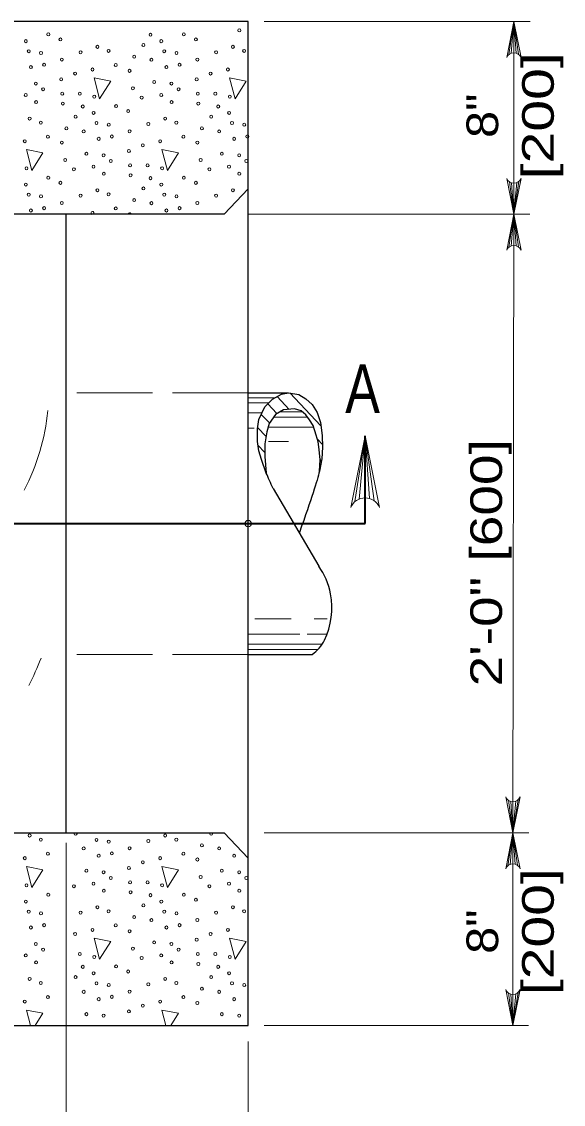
# Model space of a CAD drawing. Extents: x -410.5 to -376.5, y 1617.6 to 1661.6.
# Drawn here: x -401.85 to -399.18, y 1643.03 to 1648.36 of the extents above; entities that cross this region are included whole.
import ezdxf
from ezdxf.enums import TextEntityAlignment as Align

# ---------------------------------------------------------------- set-up
doc = ezdxf.new("R2010")
doc.units = 0
doc.header["$LTSCALE"] = 0.062
doc.header["$PDMODE"] = 32
doc.header["$PDSIZE"] = 0.031
doc.linetypes.add('LONG_DASHED', pattern=[7.5, 6, -1.5])
doc.layers.add('1', color=7, linetype='Continuous', lineweight=13)

msp = doc.modelspace()

# ---------------------------------------------------------------- linework, layer by layer
at = {"layer": '1'}
for p, q in [((-399.345, 1648.3615), (-400.65567, 1648.3615)), ((-399.44992, 1648.19942), (-399.42517, 1648.3615)), ((-399.4395, 1648.2055), (-399.42517, 1648.3615)), ((-399.42517, 1648.3615), (-399.42517, 1647.41208)), ((-399.42517, 1648.20833), (-399.42517, 1648.3615)), ((-399.41383, 1648.20667), (-399.42517, 1648.3615)), ((-399.40267, 1648.20125), (-399.42517, 1648.3615)), ((-400.74375, 1648.06817), (-400.82575, 1648.08408)), ((-399.44758, 1647.57233), (-399.42517, 1647.41208)), ((-399.43642, 1647.56692), (-399.42517, 1647.41208)), ((-399.40033, 1647.57417), (-399.42517, 1647.41208)), ((-399.41075, 1647.56808), (-399.42517, 1647.41208)), ((-399.42517, 1647.56525), (-399.42517, 1647.41208)), ((-399.3465, 1647.41208), (-400.73433, 1647.41208)), ((-399.44992, 1647.24992), (-399.42517, 1647.41208)), ((-399.4395, 1647.25608), (-399.42517, 1647.41208)), ((-399.42517, 1647.41208), (-399.42975, 1644.36383)), ((-399.42517, 1647.25892), (-399.42517, 1647.41208)), ((-399.41383, 1647.25725), (-399.42517, 1647.41208)), ((-399.40267, 1647.25183), (-399.42517, 1647.41208)), ((-400.73433, 1646.508), (-400.60125, 1646.508)), ((-400.59167, 1646.51333), (-400.53217, 1646.45025)), ((-400.529, 1646.53167), (-400.376, 1646.36975)), ((-400.73433, 1646.483), (-400.63208, 1646.483)), ((-400.63783, 1646.47725), (-400.59275, 1646.42958)), ((-400.73433, 1646.43308), (-400.66625, 1646.43308)), ((-400.6695, 1646.42608), (-400.62967, 1646.38392)), ((-400.60917, 1646.41292), (-400.4425, 1646.41292)), ((-400.57825, 1646.43792), (-400.46692, 1646.43792)), ((-400.73433, 1646.35808), (-400.704, 1646.35808)), ((-400.68775, 1646.36058), (-400.64608, 1646.31642)), ((-400.63642, 1646.36292), (-400.412, 1646.36292)), ((-400.63492, 1646.29217), (-400.536, 1646.29217)), ((-400.3935, 1646.30342), (-400.36875, 1646.27733)), ((-400.208, 1645.99633), (-400.1585, 1646.32058)), ((-400.18725, 1646.00858), (-400.1585, 1646.32058)), ((-400.1585, 1646.01425), (-400.1585, 1646.32058)), ((-400.13583, 1646.011), (-400.1585, 1646.32058)), ((-400.11367, 1646.00008), (-400.1585, 1646.32058)), ((-400.68583, 1646.27383), (-400.65225, 1646.23825)), ((-400.37992, 1646.20433), (-400.37367, 1646.19767)), ((-400.37983, 1646.20175), (-400.374, 1646.1955)), ((-400.65, 1646.151), (-400.64575, 1646.1465)), ((-400.64617, 1646.14042), (-400.645, 1646.13933)), ((-400.38167, 1646.16833), (-400.37933, 1646.16592)), ((-400.70208, 1645.41783), (-400.52225, 1645.41783)), ((-400.409, 1645.41783), (-400.34525, 1645.41783)), ((-400.73433, 1645.34283), (-400.47942, 1645.34283)), ((-400.44417, 1645.34283), (-400.34525, 1645.34283)), ((-400.73433, 1645.29283), (-400.37, 1645.29283)), ((-400.73433, 1645.26792), (-400.39025, 1645.26792)), ((-399.45217, 1644.52408), (-399.42975, 1644.36383)), ((-399.44108, 1644.51867), (-399.42975, 1644.36383)), ((-399.40492, 1644.52592), (-399.42975, 1644.36383)), ((-399.41533, 1644.51983), (-399.42975, 1644.36383)), ((-399.42975, 1644.517), (-399.42975, 1644.36383)), ((-399.35108, 1644.36383), (-400.65567, 1644.36383)), ((-399.4545, 1644.20167), (-399.42975, 1644.36383)), ((-399.44408, 1644.20783), (-399.42975, 1644.36383)), ((-399.42975, 1644.21067), (-399.42975, 1644.36383)), ((-399.41842, 1644.209), (-399.42975, 1644.36383)), ((-399.40733, 1644.20358), (-399.42975, 1644.36383)), ((-399.42975, 1644.36383), (-399.42975, 1643.41433)), ((-401.631, 1644.31375), (-401.631, 1642.69667)), ((-400.82575, 1643.84383), (-400.79875, 1643.7415)), ((-400.74375, 1643.828), (-400.82575, 1643.84383)), ((-400.79875, 1643.7415), (-400.74375, 1643.828)), ((-399.45217, 1643.57458), (-399.42975, 1643.41433)), ((-399.44108, 1643.56917), (-399.42975, 1643.41433)), ((-399.40492, 1643.5765), (-399.42975, 1643.41433)), ((-399.41533, 1643.57033), (-399.42975, 1643.41433)), ((-399.42975, 1643.5675), (-399.42975, 1643.41433)), ((-401.827, 1643.49058), (-401.80683, 1643.41433)), ((-401.745, 1643.47458), (-401.827, 1643.49058)), ((-401.78333, 1643.41433), (-401.745, 1643.47458)), ((-401.15942, 1643.49058), (-401.13933, 1643.41433)), ((-401.0775, 1643.47458), (-401.15942, 1643.49058)), ((-401.11583, 1643.41433), (-401.0775, 1643.47458)), ((-399.3525, 1643.41433), (-400.65567, 1643.41433)), ((-400.73417, 1643.33558), (-400.73417, 1642.69667))]:
    msp.add_line(p, q, dxfattribs=at)
at = {"layer": '1', "lineweight": 25}
for p, q in [((-400.8525, 1647.41208), (-400.7345, 1647.537)), ((-400.8525, 1647.41208), (-401.63108, 1647.41208)), ((-400.73433, 1646.533), (-400.5355, 1646.533)), ((-400.61067, 1646.0605), (-400.38658, 1645.67742)), ((-400.73433, 1645.24292), (-400.41833, 1645.24292)), ((-401.63108, 1644.36375), (-400.8525, 1644.36383)), ((-400.8525, 1644.36383), (-400.7345, 1644.23892))]:
    msp.add_line(p, q, dxfattribs=at)
at = {"layer": '1', "linetype": 'LONG_DASHED'}
for p, q in [((-400.73433, 1646.533), (-401.63108, 1646.533)), ((-400.73433, 1645.24292), (-401.63108, 1645.24292))]:
    msp.add_line(p, q, dxfattribs=at)
at = {"layer": '1', "lineweight": 35}
for p, q in [((-400.1585, 1645.88792), (-400.1585, 1646.32058)), ((-402.19475, 1645.88792), (-400.1585, 1645.88792))]:
    msp.add_line(p, q, dxfattribs=at)
at = {"layer": '1', "lineweight": 25}
msp.add_lwpolyline([(-405.35992, 1643.41425), (-400.73433, 1643.41425), (-400.73433, 1648.3615), (-405.35992, 1648.3615), (-405.35992, 1647.537), (-405.35992, 1644.23892)], close=True, dxfattribs=at)
at = {"layer": '1'}
for points in [[(-399.4605, 1648.1845), (-399.42517, 1648.3615), (-399.38975, 1648.1845)], [(-400.82575, 1648.08408), (-400.79875, 1647.98167), (-400.74375, 1648.06817)], [(-399.38975, 1647.58908), (-399.42517, 1647.41208), (-399.4605, 1647.58908)], [(-399.4605, 1647.23508), (-399.42517, 1647.41208), (-399.38975, 1647.23508)], [(-400.22925, 1645.96658), (-400.1585, 1646.32058), (-400.08767, 1645.96658)], [(-399.39433, 1644.54083), (-399.42975, 1644.36383), (-399.46508, 1644.54083)], [(-399.46508, 1644.18683), (-399.42975, 1644.36383), (-399.39433, 1644.18683)], [(-399.39433, 1643.59133), (-399.42975, 1643.41433), (-399.46508, 1643.59133)]]:
    msp.add_lwpolyline(points, dxfattribs=at)
for points in [[(-401.49325, 1648.08408), (-401.46625, 1647.98167), (-401.41125, 1648.06817)], [(-401.827, 1647.73075), (-401.8, 1647.62833), (-401.745, 1647.71483)], [(-401.15942, 1647.73075), (-401.13242, 1647.62833), (-401.0775, 1647.71483)], [(-401.827, 1644.19725), (-401.8, 1644.09483), (-401.745, 1644.18125)], [(-401.15942, 1644.19725), (-401.13242, 1644.09483), (-401.0775, 1644.18125)], [(-401.49325, 1643.84383), (-401.46625, 1643.7415), (-401.41125, 1643.828)]]:
    msp.add_lwpolyline(points, close=True, dxfattribs=at)
at = {"layer": '1', "lineweight": 25}
for points in [[(-404.46308, 1644.36383), (-404.46308, 1644.36375), (-401.63108, 1644.36375), (-401.63108, 1647.41208), (-404.46308, 1647.41208)], [(-400.64483, 1646.13692), (-400.66917, 1646.203), (-400.68133, 1646.24617), (-400.689, 1646.29242), (-400.68875, 1646.35433), (-400.68092, 1646.4015), (-400.6525, 1646.46275), (-400.61383, 1646.501), (-400.57067, 1646.52508), (-400.5355, 1646.533), (-400.48517, 1646.52333), (-400.4505, 1646.50292), (-400.41842, 1646.475), (-400.39408, 1646.43592), (-400.378, 1646.3865), (-400.37, 1646.32242), (-400.36833, 1646.265), (-400.37208, 1646.20617), (-400.38283, 1646.14692)], [(-400.64483, 1646.13692), (-400.66917, 1646.203), (-400.68133, 1646.24617), (-400.689, 1646.29242), (-400.68875, 1646.35433), (-400.68092, 1646.4015), (-400.6525, 1646.46275), (-400.61383, 1646.501), (-400.57067, 1646.52508), (-400.5355, 1646.533), (-400.48517, 1646.52333), (-400.4505, 1646.50292), (-400.41842, 1646.475), (-400.39408, 1646.43592), (-400.378, 1646.3865), (-400.37, 1646.32242), (-400.36833, 1646.265), (-400.37208, 1646.20617), (-400.38283, 1646.14692)], [(-400.38283, 1646.14692), (-400.37975, 1646.20275), (-400.38442, 1646.25233), (-400.38992, 1646.29025), (-400.39908, 1646.32425), (-400.41467, 1646.37092), (-400.43217, 1646.39917), (-400.4505, 1646.4235), (-400.47258, 1646.44283), (-400.50567, 1646.45258), (-400.56067, 1646.44775), (-400.60025, 1646.42542), (-400.63142, 1646.38167), (-400.6425, 1646.33983), (-400.65167, 1646.28058), (-400.65258, 1646.21925), (-400.64483, 1646.13692)], [(-400.38283, 1646.14692), (-400.37975, 1646.20275), (-400.38442, 1646.25233), (-400.38992, 1646.29025), (-400.39908, 1646.32425), (-400.41467, 1646.37092), (-400.43217, 1646.39917), (-400.4505, 1646.4235), (-400.47258, 1646.44283), (-400.50567, 1646.45258), (-400.56067, 1646.44775), (-400.60025, 1646.42542), (-400.63142, 1646.38167), (-400.6425, 1646.33983), (-400.65167, 1646.28058), (-400.65258, 1646.21925), (-400.64483, 1646.13692)]]:
    msp.add_lwpolyline(points, dxfattribs=at)
at = {"layer": '1'}
for centre, radius, start, end in [((-399.42509, 1648.17022), 0.0382, 22.08782, 157.91395), ((-399.42516, 1647.60336), 0.0382, 202.08782, 337.91395), ((-399.42509, 1647.22077), 0.0382, 22.08782, 157.91395), ((-400.1584, 1645.93802), 0.0764, 22.08782, 157.91395), ((-399.42975, 1644.55511), 0.0382, 202.08782, 337.91395), ((-399.42968, 1644.17253), 0.0382, 22.08782, 157.91395), ((-399.42975, 1643.60566), 0.0382, 202.08782, 337.91395)]:
    msp.add_arc(centre, radius, start, end, dxfattribs=at)
for centre, major_axis in [((-401.71877, 1648.29871), (0, -0.00756)), ((-401.05126, 1648.29871), (0, -0.00756)), ((-400.77786, 1648.31843), (0, -0.00756)), ((-401.82963, 1648.26531), (0, 0.00756)), ((-401.65931, 1648.27391), (0, -0.00756)), ((-401.25046, 1648.24623), (0, 0.00756)), ((-401.21525, 1648.29682), (0, 0.00756)), ((-401.16213, 1648.26531), (0, 0.00756)), ((-400.9918, 1648.27391), (0, -0.00756)), ((-401.81517, 1648.21573), (0, 0.00756)), ((-401.75482, 1648.20707), (0, -0.00756)), ((-401.55985, 1648.21066), (0, -0.00756)), ((-401.47691, 1648.23734), (0, -0.00756)), ((-401.42195, 1648.21732), (0, -0.00756)), ((-401.14766, 1648.21573), (0, 0.00756)), ((-401.08731, 1648.20707), (0, -0.00756)), ((-400.89234, 1648.21066), (0, -0.00756)), ((-400.8094, 1648.23734), (0, -0.00756)), ((-400.75444, 1648.21732), (0, -0.00756)), ((-401.73952, 1648.14894), (0, -0.00756)), ((-401.65208, 1648.17462), (0, -0.00756)), ((-401.38685, 1648.14765), (0, 0.00756)), ((-401.29579, 1648.1887), (0, 0.00756)), ((-401.2108, 1648.17374), (0, 0.00756)), ((-401.07201, 1648.14894), (0, -0.00756)), ((-400.98457, 1648.17462), (0, -0.00756)), ((-401.80444, 1648.13746), (0, -0.00756)), ((-401.58694, 1648.10566), (0, -0.00756)), ((-401.50127, 1648.12568), (0, -0.00756)), ((-401.31832, 1648.11903), (0, 0.00756)), ((-401.13693, 1648.13746), (0, -0.00756)), ((-400.91943, 1648.10566), (0, -0.00756)), ((-400.83377, 1648.12568), (0, -0.00756)), ((-401.78002, 1648.05637), (0, -0.00756)), ((-401.65536, 1648.07704), (0, -0.00756)), ((-401.30208, 1648.03316), (0, -0.00756)), ((-401.19756, 1648.06373), (0, -0.00756)), ((-401.11251, 1648.05637), (0, -0.00756)), ((-400.98785, 1648.07704), (0, -0.00756)), ((-401.82991, 1647.99977), (0, -0.00756)), ((-401.74458, 1648.02839), (0, -0.00756)), ((-401.64996, 1648.00643), (0, -0.00756)), ((-401.56341, 1648.00643), (0, 0.00756)), ((-401.49226, 1647.99212), (0, -0.00756)), ((-401.2588, 1647.98735), (0, -0.00756)), ((-401.1624, 1647.99977), (0, -0.00756)), ((-401.07707, 1648.02839), (0, -0.00756)), ((-400.98245, 1648.00643), (0, -0.00756)), ((-400.8959, 1648.00643), (0, 0.00756)), ((-400.82476, 1647.99212), (0, -0.00756)), ((-401.77913, 1647.96509), (0, -0.00756)), ((-401.64729, 1647.95778), (0, -0.00756)), ((-401.549, 1647.94347), (0, 0.00756)), ((-401.38502, 1647.94536), (0, -0.00756)), ((-401.11162, 1647.96509), (0, -0.00756)), ((-400.97978, 1647.95778), (0, -0.00756)), ((-400.88149, 1647.94347), (0, 0.00756)), ((-401.81067, 1647.88399), (0, -0.00756)), ((-401.58421, 1647.89288), (0, 0.00756)), ((-401.49588, 1647.91196), (0, 0.00756)), ((-401.32555, 1647.92056), (0, -0.00756)), ((-401.14316, 1647.88399), (0, -0.00756)), ((-400.9167, 1647.89288), (0, 0.00756)), ((-400.82837, 1647.91196), (0, 0.00756)), ((-401.75571, 1647.86397), (0, -0.00756)), ((-401.62955, 1647.83535), (0, 0.00756)), ((-401.54455, 1647.82039), (0, 0.00756)), ((-401.48142, 1647.86238), (0, 0.00756)), ((-401.42106, 1647.85372), (0, -0.00756)), ((-401.31832, 1647.82127), (0, -0.00756)), ((-401.22609, 1647.85731), (0, -0.00756)), ((-401.0882, 1647.86397), (0, -0.00756)), ((-400.96204, 1647.83535), (0, 0.00756)), ((-400.87704, 1647.82039), (0, 0.00756)), ((-400.81391, 1647.86238), (0, 0.00756)), ((-400.75355, 1647.85372), (0, -0.00756)), ((-401.83503, 1647.77233), (0, -0.00756)), ((-401.72061, 1647.7943), (0, 0.00756)), ((-401.65208, 1647.76568), (0, 0.00756)), ((-401.47068, 1647.78411), (0, -0.00756)), ((-401.40577, 1647.79559), (0, -0.00756)), ((-401.16752, 1647.77233), (0, -0.00756)), ((-401.0531, 1647.7943), (0, 0.00756)), ((-400.98457, 1647.76568), (0, 0.00756)), ((-400.80317, 1647.78411), (0, -0.00756)), ((-400.73826, 1647.79559), (0, -0.00756)), ((-401.3216, 1647.72369), (0, -0.00756)), ((-401.25318, 1647.75231), (0, -0.00756)), ((-401.63583, 1647.67981), (0, -0.00756)), ((-401.53131, 1647.71038), (0, -0.00756)), ((-401.44626, 1647.70302), (0, -0.00756)), ((-401.41083, 1647.67504), (0, -0.00756)), ((-400.96833, 1647.67981), (0, -0.00756)), ((-400.8638, 1647.71038), (0, -0.00756)), ((-400.77875, 1647.70302), (0, -0.00756)), ((-400.74332, 1647.67504), (0, -0.00756)), ((-401.82602, 1647.63877), (0, -0.00756)), ((-401.59256, 1647.634), (0, -0.00756)), ((-401.49616, 1647.64642), (0, -0.00756)), ((-401.44537, 1647.61174), (0, -0.00756)), ((-401.31621, 1647.65308), (0, -0.00756)), ((-401.22965, 1647.65308), (0, 0.00756)), ((-401.15851, 1647.63877), (0, -0.00756)), ((-400.92505, 1647.634), (0, -0.00756)), ((-400.82865, 1647.64642), (0, -0.00756)), ((-400.77786, 1647.61174), (0, -0.00756)), ((-401.82963, 1647.55861), (0, 0.00756)), ((-401.71877, 1647.59201), (0, -0.00756)), ((-401.65931, 1647.56721), (0, -0.00756)), ((-401.31354, 1647.60443), (0, -0.00756)), ((-401.21525, 1647.59012), (0, 0.00756)), ((-401.16213, 1647.55861), (0, 0.00756)), ((-401.05126, 1647.59201), (0, -0.00756)), ((-400.9918, 1647.56721), (0, -0.00756)), ((-401.81517, 1647.50903), (0, 0.00756)), ((-401.75482, 1647.50037), (0, -0.00756)), ((-401.55985, 1647.50396), (0, -0.00756)), ((-401.47691, 1647.53064), (0, -0.00756)), ((-401.42195, 1647.51062), (0, -0.00756)), ((-401.25046, 1647.53953), (0, 0.00756)), ((-401.14766, 1647.50903), (0, 0.00756)), ((-401.08731, 1647.50037), (0, -0.00756)), ((-400.89234, 1647.50396), (0, -0.00756)), ((-400.8094, 1647.53064), (0, -0.00756)), ((-401.65208, 1647.46792), (0, -0.00756)), ((-401.29579, 1647.482), (0, 0.00756)), ((-401.2108, 1647.46704), (0, 0.00756)), ((-400.98457, 1647.46792), (0, -0.00756)), ((-401.80444, 1647.43076), (0, -0.00756)), ((-401.73952, 1647.44225), (0, -0.00756)), ((-401.38685, 1647.44095), (0, 0.00756)), ((-401.13693, 1647.43076), (0, -0.00756)), ((-401.07201, 1647.44225), (0, -0.00756)), ((-401.81067, 1644.35049), (0, -0.00756)), ((-401.14316, 1644.35049), (0, -0.00756)), ((-401.75571, 1644.33047), (0, -0.00756)), ((-401.48142, 1644.32888), (0, 0.00756)), ((-401.42106, 1644.32022), (0, -0.00756)), ((-401.22609, 1644.32382), (0, -0.00756)), ((-401.0882, 1644.33047), (0, -0.00756)), ((-400.96204, 1644.30185), (0, 0.00756)), ((-401.72061, 1644.2608), (0, 0.00756)), ((-401.54455, 1644.28689), (0, 0.00756)), ((-401.47068, 1644.25061), (0, -0.00756)), ((-401.40577, 1644.2621), (0, -0.00756)), ((-401.31832, 1644.28777), (0, -0.00756)), ((-401.0531, 1644.2608), (0, 0.00756)), ((-400.87704, 1644.28689), (0, 0.00756)), ((-400.80317, 1644.25061), (0, -0.00756)), ((-401.83503, 1644.23883), (0, -0.00756)), ((-401.3216, 1644.19019), (0, -0.00756)), ((-401.25318, 1644.21881), (0, -0.00756)), ((-401.16752, 1644.23883), (0, -0.00756)), ((-400.98457, 1644.23218), (0, 0.00756)), ((-401.53131, 1644.17688), (0, -0.00756)), ((-401.44626, 1644.16952), (0, -0.00756)), ((-401.41083, 1644.14155), (0, -0.00756)), ((-400.96833, 1644.14632), (0, -0.00756)), ((-400.8638, 1644.17688), (0, -0.00756)), ((-400.77875, 1644.16952), (0, -0.00756)), ((-400.74332, 1644.14155), (0, -0.00756)), ((-401.82602, 1644.10527), (0, -0.00756)), ((-401.59256, 1644.1005), (0, -0.00756)), ((-401.49616, 1644.11292), (0, -0.00756)), ((-401.31621, 1644.11958), (0, -0.00756)), ((-401.22965, 1644.11958), (0, 0.00756)), ((-401.15851, 1644.10527), (0, -0.00756)), ((-400.92505, 1644.1005), (0, -0.00756)), ((-400.82865, 1644.11292), (0, -0.00756)), ((-401.71877, 1644.05851), (0, -0.00756)), ((-401.44537, 1644.07824), (0, -0.00756)), ((-401.31354, 1644.07093), (0, -0.00756)), ((-401.21525, 1644.05662), (0, 0.00756)), ((-401.05126, 1644.05851), (0, -0.00756)), ((-400.9918, 1644.03371), (0, -0.00756)), ((-400.77786, 1644.07824), (0, -0.00756)), ((-401.82963, 1644.02512), (0, 0.00756)), ((-401.47691, 1643.99714), (0, -0.00756)), ((-401.42195, 1643.97712), (0, -0.00756)), ((-401.25046, 1644.00604), (0, 0.00756)), ((-401.16213, 1644.02512), (0, 0.00756)), ((-400.8094, 1643.99714), (0, -0.00756)), ((-400.75444, 1643.97712), (0, -0.00756)), ((-401.81517, 1643.97553), (0, 0.00756)), ((-401.75482, 1643.96687), (0, -0.00756)), ((-401.55985, 1643.97047), (0, -0.00756)), ((-401.29579, 1643.9485), (0, 0.00756)), ((-401.2108, 1643.93354), (0, 0.00756)), ((-401.14766, 1643.97553), (0, 0.00756)), ((-401.08731, 1643.96687), (0, -0.00756)), ((-400.98457, 1643.93442), (0, -0.00756)), ((-400.89234, 1643.97047), (0, -0.00756)), ((-401.80444, 1643.89726), (0, -0.00756)), ((-401.73952, 1643.90875), (0, -0.00756)), ((-401.50127, 1643.88548), (0, -0.00756)), ((-401.38685, 1643.90745), (0, 0.00756)), ((-401.31832, 1643.87883), (0, 0.00756)), ((-401.13693, 1643.89726), (0, -0.00756)), ((-401.07201, 1643.90875), (0, -0.00756)), ((-400.83377, 1643.88548), (0, -0.00756)), ((-401.78002, 1643.81617), (0, -0.00756)), ((-401.58694, 1643.86546), (0, -0.00756)), ((-401.19756, 1643.82353), (0, -0.00756)), ((-401.11251, 1643.81617), (0, -0.00756)), ((-400.98785, 1643.83684), (0, -0.00756)), ((-400.91943, 1643.86546), (0, -0.00756)), ((-401.74458, 1643.7882), (0, -0.00756)), ((-401.56341, 1643.76623), (0, 0.00756)), ((-401.30208, 1643.79297), (0, -0.00756)), ((-401.07707, 1643.7882), (0, -0.00756)), ((-400.98245, 1643.76623), (0, -0.00756)), ((-400.8959, 1643.76623), (0, 0.00756)), ((-401.82991, 1643.75957), (0, -0.00756)), ((-401.77913, 1643.72489), (0, -0.00756)), ((-401.49226, 1643.75192), (0, -0.00756)), ((-401.2588, 1643.74715), (0, -0.00756)), ((-401.1624, 1643.75957), (0, -0.00756)), ((-401.11162, 1643.72489), (0, -0.00756)), ((-400.97978, 1643.71758), (0, -0.00756)), ((-400.82476, 1643.75192), (0, -0.00756)), ((-401.549, 1643.70327), (0, 0.00756)), ((-401.49588, 1643.67177), (0, 0.00756)), ((-401.38502, 1643.70516), (0, -0.00756)), ((-401.32555, 1643.68037), (0, -0.00756)), ((-400.88149, 1643.70327), (0, 0.00756)), ((-400.82837, 1643.67177), (0, 0.00756)), ((-401.81067, 1643.64379), (0, -0.00756)), ((-401.75571, 1643.62377), (0, -0.00756)), ((-401.58421, 1643.65269), (0, 0.00756)), ((-401.48142, 1643.62218), (0, 0.00756)), ((-401.42106, 1643.61352), (0, -0.00756)), ((-401.22609, 1643.61712), (0, -0.00756)), ((-401.14316, 1643.64379), (0, -0.00756)), ((-401.0882, 1643.62377), (0, -0.00756)), ((-400.9167, 1643.65269), (0, 0.00756)), ((-400.81391, 1643.62218), (0, 0.00756)), ((-400.75355, 1643.61352), (0, -0.00756)), ((-401.72061, 1643.5541), (0, 0.00756)), ((-401.54455, 1643.58019), (0, 0.00756)), ((-401.40577, 1643.5554), (0, -0.00756)), ((-401.31832, 1643.58107), (0, -0.00756)), ((-401.0531, 1643.5541), (0, 0.00756)), ((-400.96204, 1643.59515), (0, 0.00756)), ((-400.87704, 1643.58019), (0, 0.00756)), ((-401.83503, 1643.53213), (0, -0.00756)), ((-401.47068, 1643.54391), (0, -0.00756)), ((-401.25318, 1643.51211), (0, -0.00756)), ((-401.16752, 1643.53213), (0, -0.00756)), ((-400.98457, 1643.52548), (0, 0.00756)), ((-400.80317, 1643.54391), (0, -0.00756)), ((-401.53131, 1643.47018), (0, -0.00756)), ((-401.44626, 1643.46282), (0, -0.00756)), ((-401.3216, 1643.48349), (0, -0.00756)), ((-400.8638, 1643.47018), (0, -0.00756)), ((-400.77875, 1643.46282), (0, -0.00756))]:
    msp.add_ellipse(centre, major_axis=major_axis, ratio=0.944543, dxfattribs=at)
for centre, major_axis, start_param, end_param in [((-401.50131, 1647.41898), (0, -0.00756), 0.4597322, 5.9244258), ((-401.31834, 1647.41231), (0, 0.00756), 4.8124583, 8.0199611), ((-402.67082, 1646.54358), (0, 1.0097), 4.2038228, 4.6151372), ((-402.84629, 1645.68719), (0, 1.24478), 4.2121561, 4.331539), ((-401.58423, 1644.35932), (0, 0.00756), 0.9463754, 5.3310213), ((-400.91674, 1644.35932), (0, 0.00756), 0.9399206, 5.3374759)]:
    msp.add_ellipse(centre, major_axis=major_axis, ratio=0.944543, start_param=start_param, end_param=end_param, dxfattribs=at)
at = {"layer": '1', "lineweight": 25}
for centre, major_axis, start_param, end_param in [((-400.62962, 1645.47865), (0, 0.3251), 4.9073919, 5.370128), ((-400.66203, 1645.47304), (0, 0.35983), 4.2528342, 4.9042115), ((-400.53553, 1645.42102), (0, -0.21709), 0.608535, 1.0523476)]:
    msp.add_ellipse(centre, major_axis=major_axis, ratio=0.944543, start_param=start_param, end_param=end_param, dxfattribs=at)
for points in [[(-400.61067, 1646.0605), (-400.62408, 1646.08867), (-400.63533, 1646.11408), (-400.64483, 1646.13692)], [(-400.38283, 1646.14692), (-400.39542, 1646.09542), (-400.42183, 1646.01267), (-400.48167, 1645.84458)]]:
    msp.add_open_spline(points, degree=3, dxfattribs=at)
at = {"layer": '1'}
msp.add_point((-400.73433, 1645.88792), dxfattribs=at)

# ---------------------------------------------------------------- texts
for s, width, p in [('[200]', 1.35, (-399.22875, 1647.89758)), ('8"', 1.15, (-399.50275, 1647.89758)), ('[200]', 1.35, (-399.22875, 1643.87658)), ('8"', 1.15, (-399.50275, 1643.87658))]:
    msp.add_text(s, height=0.156, rotation=90, dxfattribs=dict(at, width=width)).set_placement(p, align=Align.CENTER)
at = {"layer": '1', "width": 0.8}
msp.add_text('A', height=0.24, dxfattribs=at).set_placement((-400.17075, 1646.43217), align=Align.CENTER)
at = {"layer": '1', "width": 1.3}
msp.add_text('2\'-0" [600]', height=0.156, rotation=90, dxfattribs=at).set_placement((-399.48358, 1645.08542))

doc.saveas('drawing.dxf')
